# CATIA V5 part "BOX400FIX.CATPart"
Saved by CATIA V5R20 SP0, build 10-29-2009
Part number: BOX400FIX
Bounding box of the stored display mesh (mm): x 0 to 540.5, y 0 to 70, z -20 to 45
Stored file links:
  C:\Users\Utente\Desktop\IO LAVORO\3D X SITO CF\X SITO\PLASTICA\BOX\BOX400FIX.CATPart
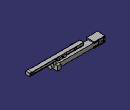
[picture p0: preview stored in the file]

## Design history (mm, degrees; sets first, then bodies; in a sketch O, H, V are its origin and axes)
Set1
  DatumSurface1 to DatumSurface66 "_ZH 91/A1"
  DatumSurface67 to DatumSurface129 "_ZH 91/B2"
Body1 (main body)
